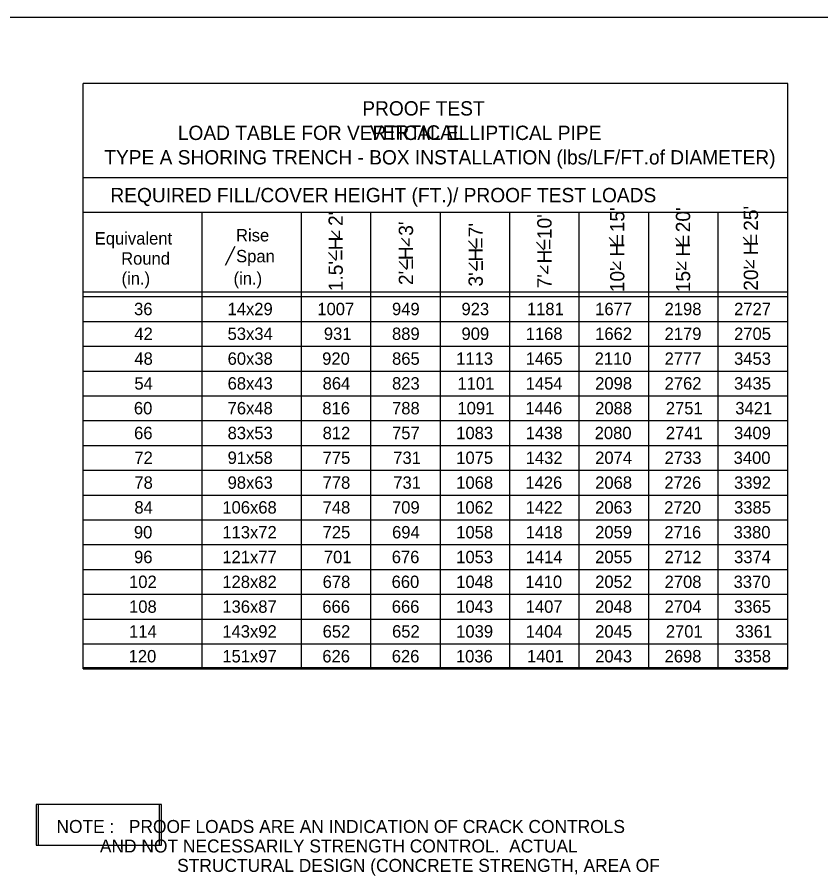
# Model space of a CAD drawing. Extents: x -22562 to -18409, y 3991 to 7171.
# Drawn here: x -19319.2 to -19140.8, y 6161.8 to 6352.4 of the extents above; entities that cross this region are included whole.
import ezdxf

# ---------------------------------------------------------------- set-up
doc = ezdxf.new("R2010")
doc.units = 0
for name, color, linetype in [('1', 7, 'Continuous'), ('2', 7, 'Continuous'), ('3', 7, 'Continuous'), ('4', 7, 'Continuous')]:
    doc.layers.add(name, color=color, linetype=linetype)

msp = doc.modelspace()

# ---------------------------------------------------------------- linework, layer by layer
at = {"layer": '1'}
for p, q in [((-19247.69, 6303.16), (-19249.41, 6304.93)), ((-19247.69, 6303.16), (-19247.69, 6304.92)), ((-19232.2, 6301.52), (-19233.92, 6303.29)), ((-19232.2, 6301.52), (-19232.2, 6303.28)), ((-19217.32, 6300.96), (-19219.04, 6302.73)), ((-19202.26, 6300.68), (-19203.98, 6302.45)), ((-19186.12, 6301.67), (-19187.84, 6303.44)), ((-19171.38, 6301.53), (-19173.1, 6303.3)), ((-19156.39, 6301.8), (-19158.11, 6303.57)), ((-19273, 6297.35), (-19270.81, 6301.58)), ((-19248.41, 6298.36), (-19250.13, 6300.13)), ((-19155.79, 6296.64), (-19157.51, 6298.41)), ((-19155.74, 6296.65), (-19155.74, 6298.41)), ((-19232.7, 6296.39), (-19234.42, 6298.15)), ((-19217.22, 6296.05), (-19218.94, 6297.82)), ((-19201.43, 6295.42), (-19203.15, 6297.19)), ((-19201.42, 6295.42), (-19201.42, 6297.18)), ((-19185.31, 6296.31), (-19187.03, 6298.08)), ((-19185.28, 6296.39), (-19185.28, 6298.15)), ((-19170.9, 6296.29), (-19172.62, 6298.06)), ((-19170.82, 6296.32), (-19170.82, 6298.08))]:
    msp.add_line(p, q, dxfattribs=at)
for points in [[(-19315.02, 6168.64), (-19287.63, 6168.64), (-19287.63, 6177.66), (-19315.02, 6177.66)], [(-19314.57, 6168.64), (-19287.18, 6168.64), (-19287.18, 6177.66), (-19314.57, 6177.66)]]:
    msp.add_lwpolyline(points, close=True, dxfattribs=at)
at = {"layer": '2'}
for p, q in [((-19503.85, 6352.37), (-18717.85, 6352.37)), ((-19304.57, 6207.76), (-19304.57, 6337.62)), ((-19148.18, 6337.62), (-19304.57, 6337.62)), ((-19148.18, 6207.76), (-19148.18, 6337.62)), ((-19148.18, 6316.73), (-19304.57, 6316.73)), ((-19148.18, 6309.02), (-19304.57, 6309.02)), ((-19278.14, 6207.76), (-19278.14, 6309.02)), ((-19256.11, 6207.76), (-19256.11, 6309.02)), ((-19240.7, 6207.76), (-19240.7, 6309.02)), ((-19225.28, 6207.76), (-19225.28, 6309.02)), ((-19209.86, 6207.76), (-19209.86, 6309.02)), ((-19194.44, 6207.76), (-19194.44, 6309.02)), ((-19179.02, 6207.76), (-19179.02, 6309.02)), ((-19163.6, 6207.76), (-19163.6, 6309.02)), ((-19304.57, 6291.4), (-19148.18, 6291.4)), ((-19304.57, 6290.36), (-19148.18, 6290.36)), ((-19304.57, 6284.85), (-19148.18, 6284.85)), ((-19304.57, 6284.85), (-19148.18, 6284.85)), ((-19304.57, 6279.35), (-19148.18, 6279.35)), ((-19304.57, 6273.84), (-19148.18, 6273.84)), ((-19304.57, 6268.34), (-19148.18, 6268.34)), ((-19304.57, 6262.83), (-19148.18, 6262.83)), ((-19304.57, 6257.32), (-19148.18, 6257.32)), ((-19304.57, 6251.82), (-19148.18, 6251.82)), ((-19304.57, 6246.31), (-19148.18, 6246.31)), ((-19304.57, 6240.8), (-19148.18, 6240.8)), ((-19304.57, 6235.3), (-19148.18, 6235.3)), ((-19304.57, 6229.79), (-19148.18, 6229.79)), ((-19304.57, 6224.28), (-19148.18, 6224.28)), ((-19304.57, 6218.78), (-19148.18, 6218.78)), ((-19304.57, 6213.27), (-19148.18, 6213.27)), ((-19148.18, 6207.98), (-19304.57, 6207.98)), ((-19304.57, 6207.76), (-19148.18, 6207.76))]:
    msp.add_line(p, q, dxfattribs=at)

# ---------------------------------------------------------------- texts
at = {"layer": '1'}
for s, height, p in [('VERTICAL', 3.178, (-19240.91, 6325.19)), ('Equivalent', 2.751, (-19301.99, 6301.91)), ('Rise', 2.751, (-19270.63, 6302.6)), ('Round', 2.751, (-19296.13, 6297.44)), ('Span', 2.751, (-19270.61, 6297.96)), ('(in.)', 2.751, (-19296.04, 6293.03)), ('(in.)', 2.751, (-19271.18, 6293.03)), (' NOTE :   PROOF LOADS ARE AN INDICATION OF CRACK CONTROLS', 2.8834, (-19311.56, 6171.31)), ('          AND NOT NECESSARILY STRENGTH CONTROL.  ACTUAL', 2.8834, (-19311.56, 6166.98)), ('STRUCTURAL DESIGN (CONCRETE STRENGTH, AREA OF ', 2.8834, (-19283.7, 6162.67))]:
    msp.add_text(s, height=height, dxfattribs=at).set_placement(p)
for p in [(-19183.92, 6301.73), (-19154.23, 6301.83), (-19215.17, 6301.01), (-19200.08, 6300.7), (-19169.25, 6301.59), (-19246.27, 6298.33), (-19230.56, 6296.36), (-19215.08, 6296.02)]:
    msp.add_text('=', height=3.17, rotation=90, dxfattribs=at).set_placement(p)
at = {"layer": '3'}
for s, p in [('36', (-19293.26, 6286.23)), ('14x29', (-19272.51, 6286.23)), ('1007', (-19252.59, 6286.23)), ('949', (-19236.01, 6286.23)), ('923', (-19220.59, 6286.23)), ('1181', (-19206.07, 6286.23)), ('1677', (-19190.92, 6286.23)), ('2198', (-19175.51, 6286.23)), ('2727', (-19160.09, 6286.23)), ('42', (-19293.19, 6280.73)), ('53x34', (-19272.5, 6280.73)), ('931', (-19251.14, 6280.73)), ('889', (-19236.01, 6280.73)), ('909', (-19220.59, 6280.73)), ('1168', (-19206.34, 6280.73)), ('1662', (-19190.92, 6280.73)), ('2179', (-19175.52, 6280.73)), ('2705', (-19160.09, 6280.73)), ('48', (-19293.19, 6275.22)), ('60x38', (-19272.5, 6275.22)), ('920', (-19251.51, 6275.22)), ('865', (-19236, 6275.22)), ('1113', (-19221.76, 6275.22)), ('1465', (-19206.34, 6275.22)), ('2110', (-19191.03, 6275.22)), ('2777', (-19175.51, 6275.22)), ('3453', (-19160.09, 6275.22)), ('54', (-19293.19, 6269.72)), ('68x43', (-19272.5, 6269.72)), ('864', (-19251.41, 6269.72)), ('823', (-19236, 6269.72)), ('1101', (-19221.49, 6269.72)), ('1454', (-19206.34, 6269.72)), ('2098', (-19190.92, 6269.72)), ('2762', (-19175.51, 6269.72)), ('3435', (-19160.09, 6269.72)), ('60', (-19293.3, 6264.22)), ('76x48', (-19272.5, 6264.22)), ('816', (-19251.48, 6264.22)), ('788', (-19236, 6264.22)), ('1091', (-19221.49, 6264.22)), ('1446', (-19206.41, 6264.22)), ('2088', (-19190.92, 6264.22)), ('2751', (-19175.24, 6264.22)), ('3421', (-19159.82, 6264.22)), ('66', (-19293.26, 6258.71)), ('83x53', (-19272.5, 6258.71)), ('812', (-19251.41, 6258.71)), ('757', (-19236, 6258.71)), ('1083', (-19221.76, 6258.71)), ('1438', (-19206.34, 6258.71)), ('2080', (-19191.03, 6258.71)), ('2741', (-19175.24, 6258.71)), ('3409', (-19160.1, 6258.71)), ('72', (-19293.19, 6253.21)), ('91x58', (-19272.5, 6253.21)), ('775', (-19251.41, 6253.21)), ('731', (-19235.73, 6253.21)), ('1075', (-19221.76, 6253.21)), ('1432', (-19206.34, 6253.21)), ('2074', (-19190.92, 6253.21)), ('2733', (-19175.51, 6253.21)), ('3400', (-19160.19, 6253.21)), ('78', (-19293.19, 6247.7)), ('98x63', (-19272.5, 6247.7)), ('778', (-19251.41, 6247.7)), ('731', (-19235.73, 6247.7)), ('1068', (-19221.76, 6247.7)), ('1426', (-19206.41, 6247.7)), ('2068', (-19190.92, 6247.7)), ('2726', (-19175.57, 6247.7)), ('3392', (-19160.09, 6247.7)), ('84', (-19293.19, 6242.2)), ('106x68', (-19273.67, 6242.2)), ('748', (-19251.41, 6242.2)), ('709', (-19236.01, 6242.2)), ('1062', (-19221.76, 6242.2)), ('1422', (-19206.34, 6242.2)), ('2063', (-19190.92, 6242.2)), ('2720', (-19175.61, 6242.2)), ('3385', (-19160.09, 6242.2)), ('90', (-19293.3, 6236.69)), ('113x72', (-19273.67, 6236.69)), ('725', (-19251.41, 6236.69)), ('694', (-19236, 6236.69)), ('1058', (-19221.76, 6236.69)), ('1418', (-19206.34, 6236.69)), ('2059', (-19190.93, 6236.7)), ('2716', (-19175.57, 6236.69)), ('3380', (-19160.19, 6236.69)), ('96', (-19293.26, 6231.19)), ('121x77', (-19273.67, 6231.19)), ('701', (-19251.14, 6231.19)), ('676', (-19236.07, 6231.19)), ('1053', (-19221.76, 6231.19)), ('1414', (-19206.34, 6231.19)), ('2055', (-19190.92, 6231.19)), ('2712', (-19175.51, 6231.19)), ('3374', (-19160.09, 6231.19)), ('102', (-19294.37, 6225.68)), ('128x82', (-19273.67, 6225.68)), ('678', (-19251.41, 6225.68)), ('660', (-19236.1, 6225.68)), ('1048', (-19221.76, 6225.68)), ('1410', (-19206.44, 6225.68)), ('2052', (-19190.92, 6225.69)), ('2708', (-19175.51, 6225.68)), ('3370', (-19160.19, 6225.68)), ('108', (-19294.37, 6220.18)), ('136x87', (-19273.67, 6220.18)), ('666', (-19251.48, 6220.18)), ('666', (-19236.07, 6220.18)), ('1043', (-19221.76, 6220.18)), ('1407', (-19206.34, 6220.18)), ('2048', (-19190.92, 6220.18)), ('2704', (-19175.51, 6220.18)), ('3365', (-19160.09, 6220.18)), ('114', (-19294.37, 6214.68)), ('143x92', (-19273.67, 6214.68)), ('652', (-19251.41, 6214.68)), ('652', (-19236, 6214.68)), ('1039', (-19221.77, 6214.68)), ('1404', (-19206.34, 6214.68)), ('2045', (-19190.92, 6214.68)), ('2701', (-19175.24, 6214.68)), ('3361', (-19159.82, 6214.68)), ('120', (-19294.47, 6209.17)), ('151x97', (-19273.67, 6209.17)), ('626', (-19251.48, 6209.17)), ('626', (-19236.07, 6209.17)), ('1036', (-19221.83, 6209.17)), ('1401', (-19206.07, 6209.17)), ('2043', (-19190.92, 6209.17)), ('2698', (-19175.51, 6209.17)), ('3358', (-19160.09, 6209.17))]:
    msp.add_text(s, height=2.751, dxfattribs=at).set_placement(p)
at = {"layer": '4'}
for s, height, p in [('PROOF TEST', 3.178, (-19242.61, 6330.54)), ('LOAD TABLE FOR VERTICAL ELLIPTICAL PIPE', 3.1784, (-19283.55, 6325.11)), ('TYPE A SHORING TRENCH - BOX INSTALLATION (lbs/LF/FT.of DIAMETER)', 3.1778, (-19299.87, 6319.68)), ('REQUIRED FILL/COVER HEIGHT (FT.)/ PROOF TEST LOADS', 3.1784, (-19298.51, 6311.29))]:
    msp.add_text(s, height=height, dxfattribs=at).set_placement(p)
for s, height, p in [("10'  H  15'", 3.1717, (-19184.44, 6291.33)), ("15'  H  20'", 3.1717, (-19169.84, 6291.33)), ("20'  H  25'", 3.1717, (-19154.78, 6291.66)), ("1.5'  H  2'", 3.1717, (-19246.93, 6291.55)), ("7'  H  10'", 3.172, (-19200.6, 6292.17)), ("2'  H  3'", 3.172, (-19231.34, 6292.91)), ("3'  H  7'", 3.172, (-19215.86, 6292.58))]:
    msp.add_text(s, height=height, rotation=90, dxfattribs=at).set_placement(p)

doc.saveas('drawing.dxf')
